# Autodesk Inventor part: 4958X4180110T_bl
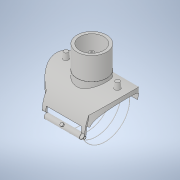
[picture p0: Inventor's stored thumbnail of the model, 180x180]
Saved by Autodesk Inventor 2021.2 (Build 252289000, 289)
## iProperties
Created: 2020-06
Part Number: 4958X4180110T_bl
Material: Generic
Description: Plasson Branch Saddle 180x110
Document SubType Name: Modeling
Designer: KIM
Density: 1 g/cm^3
Appearance: Default
Author: KIM
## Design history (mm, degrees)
derived "4958X4.ipt"
feature "Solid1::4958X4.ipt" dims "ScaleForDerivedMember" = 10
tag "TaggingFeature1"
body "Solid1"
other parameters: "d0" = 263 [user parameter], "d3" = 209.4 [user parameter], "d7" = 89 [user parameter], "d9" = 84 [user parameter], "d10" = 0.5 [user parameter], "d11" = 1 [user parameter], "d12" = 27.5 [user parameter], "d13" = 16 [user parameter], "d14" = 8 [user parameter], "d16" = 10 deg [user parameter], "d17" = 10 deg [user parameter], "d19" = 0 [user parameter], "d23" = 0 [user parameter], "d26" = 0 [user parameter], "d27" = 157.8 [user parameter], "d28" = 0 [user parameter], "d29" = 131.5 [user parameter], "d30" = 0 [user parameter], "d31" = 1 [user parameter], "d32" = 1 [user parameter], "d33" = 19.2 [user parameter], "d34" = 9.6 [user parameter], "d35" = 45 deg [user parameter], "d36" = 131.5 [user parameter], "d37" = 0 [user parameter], "d38" = 5 [user parameter], "d39" = 85 deg [user parameter], "d40" = 27.5 [user parameter], "d41" = 16 [user parameter], "d42" = 95.63636 [user parameter], "d49" = 3 [user parameter], "d50" = 6 [user parameter], "d51" = 5 [user parameter], "d54" = 0 [user parameter], "d57" = 35 deg [user parameter], "d60" = 16.4375 [user parameter], "d61" = 1 [user parameter], "d62" = 90 deg [user parameter], "d63" = 2 [user parameter], "d64" = 0 [user parameter], "d65" = 0 [user parameter], "d68" = 32.875 [user parameter], "d70" = 0.57711 [user parameter], "d71" = 10 deg [user parameter], "d73" = 5.145 [user parameter], "B" = 229 [user parameter], "L" = 263 [user parameter], "LS" = 84 [user parameter], "Dt" = 16 [user parameter], "di" = 89 [user parameter], "d72" = 14.7 [user parameter]
